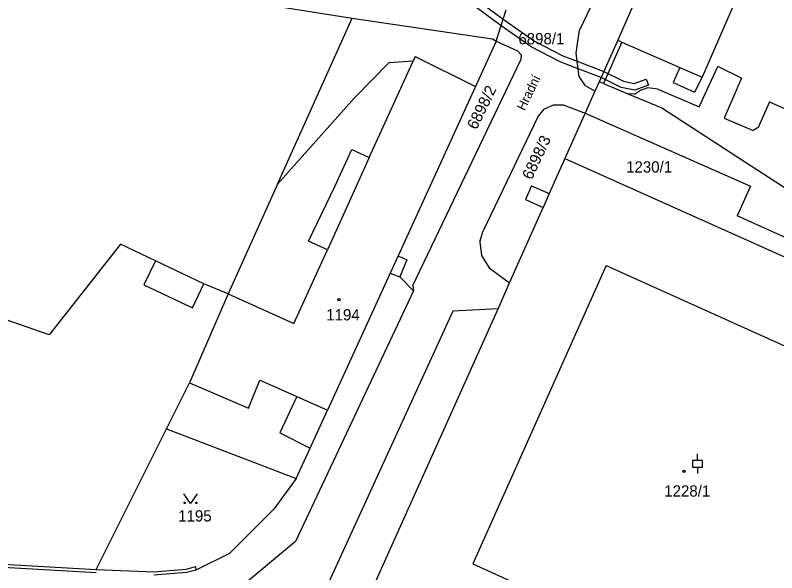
# Model space of a CAD drawing. Extents: x -593183 to -588034, y -1130415 to -1124994.
# Drawn here: x -590909.7 to -590794.7, y -1129085.7 to -1129001.6 of the extents above; entities that cross this region are included whole.
import ezdxf

# ---------------------------------------------------------------- set-up
doc = ezdxf.new("R2010")
doc.units = 0
for name, color, linetype in [('Vrstva 1', 7, 'Continuous'), ('Vrstva 15', 7, 'Continuous'), ('Vrstva 18', 7, 'Continuous'), ('Vrstva 19', 7, 'Continuous'), ('Vrstva 25', 7, 'Continuous'), ('Vrstva 27', 7, 'Continuous'), ('Vrstva 4', 7, 'Continuous')]:
    doc.layers.add(name, color=color, linetype=linetype)

msp = doc.modelspace()

# ---------------------------------------------------------------- linework, layer by layer
at = {"layer": 'Vrstva 1'}
for p, q in [((-590794.6, -1128950.4), (-590818.7, -1129005.38)), ((-590799.57, -1128951.88), (-590824.5, -1129003.84)), ((-590905.87, -1128994.54), (-590858.8, -1129002.06)), ((-590837.04, -1129005.53), (-590835.56, -1129000.8)), ((-590870.07, -1129027.1), (-590858.8, -1129002.06)), ((-590858.8, -1129002.06), (-590837.64, -1129005.16)), ((-590824.98, -1129007.35), (-590824.5, -1129003.84)), ((-590837.04, -1129005.53), (-590840.17, -1129012.37)), ((-590837.64, -1129005.16), (-590837.04, -1129005.53)), ((-590837.04, -1129005.53), (-590833.84, -1129006.96)), ((-590818.7, -1129005.38), (-590821.51, -1129011.66)), ((-590833.84, -1129006.96), (-590833.31, -1129007.56)), ((-590824.51, -1129010.86), (-590824.98, -1129007.35)), ((-590849.64, -1129042.41), (-590833.34, -1129008.35)), ((-590833.31, -1129007.56), (-590833.34, -1129008.35)), ((-590806.41, -1129015.41), (-590803.6, -1129009.34)), ((-590800, -1129011.09), (-590803.6, -1129009.34)), ((-590823.56, -1129012.26), (-590824.51, -1129010.86)), ((-590821.51, -1129011.66), (-590822.14, -1129013.08)), ((-590820.87, -1129011.93), (-590821.51, -1129011.66)), ((-590820.87, -1129011.93), (-590817.17, -1129013.47)), ((-590800, -1129011.09), (-590802.65, -1129017.15)), ((-590840.17, -1129012.37), (-590851.87, -1129037.93)), ((-590822.14, -1129013.08), (-590823.62, -1129016.37)), ((-590822.14, -1129013.08), (-590823.56, -1129012.26)), ((-590816.16, -1129013.5), (-590815.43, -1129012.99)), ((-590814.16, -1129012.57), (-590815.43, -1129012.99)), ((-590812.62, -1129012.75), (-590814.16, -1129012.57)), ((-590812.62, -1129012.75), (-590806.41, -1129015.41)), ((-590816.16, -1129013.5), (-590817.17, -1129013.47)), ((-590817.17, -1129013.47), (-590812.05, -1129015.6)), ((-590829.75, -1129015.71), (-590828.42, -1129015.11)), ((-590828.42, -1129015.11), (-590826.94, -1129015.13)), ((-590826.94, -1129015.13), (-590823.62, -1129016.37)), ((-590795.79, -1129014.65), (-590797.51, -1129018.56)), ((-590795.79, -1129014.65), (-590764.3, -1129028.78)), ((-590830.78, -1129016.94), (-590829.75, -1129015.71)), ((-590823.62, -1129016.37), (-590823.77, -1129016.71)), ((-590823.62, -1129016.37), (-590798.64, -1129027.39)), ((-590812.05, -1129015.6), (-590770.33, -1129042.68)), ((-590830.78, -1129016.94), (-590839.02, -1129034.14)), ((-590823.77, -1129016.71), (-590826.68, -1129023.22)), ((-590802.65, -1129017.15), (-590798.22, -1129019.01)), ((-590797.51, -1129018.56), (-590798.22, -1129019.01)), ((-590826.68, -1129023.22), (-590829.04, -1129028.52)), ((-590826.68, -1129023.22), (-590760.68, -1129052.84)), ((-590904.57, -1129049.84), (-590970.73, -1129026.91)), ((-590870.07, -1129027.1), (-590877.54, -1129043.64)), ((-590798.64, -1129027.39), (-590800.66, -1129031.89)), ((-590829.04, -1129028.52), (-590829.97, -1129030.61)), ((-590835.03, -1129041.99), (-590829.97, -1129030.61)), ((-590768.75, -1129046.27), (-590800.66, -1129031.89)), ((-590839.51, -1129035.82), (-590839.02, -1129034.14)), ((-590893.79, -1129036.15), (-590904.57, -1129049.84)), ((-590888.52, -1129038.67), (-590893.79, -1129036.15)), ((-590839.51, -1129035.82), (-590839.27, -1129037.84)), ((-590851.87, -1129037.93), (-590853.07, -1129040.55)), ((-590839.27, -1129037.84), (-590838.13, -1129039.72)), ((-590881.23, -1129042.15), (-590888.52, -1129038.67)), ((-590853.07, -1129040.55), (-590862.53, -1129061.21)), ((-590853.07, -1129040.55), (-590851.59, -1129041.1)), ((-590838.13, -1129039.72), (-590835.03, -1129041.99)), ((-590851.59, -1129041.1), (-590849.54, -1129043.19)), ((-590877.54, -1129043.64), (-590881.23, -1129042.15)), ((-590849.64, -1129042.41), (-590849.54, -1129043.19)), ((-590836.78, -1129045.92), (-590835.03, -1129041.99)), ((-590877.54, -1129043.64), (-590883.4, -1129057.07)), ((-590849.54, -1129043.19), (-590867.38, -1129081.05)), ((-590843.6, -1129046.27), (-590866.67, -1129096.56)), ((-590857.65, -1129092.4), (-590836.78, -1129045.92)), ((-590836.78, -1129045.92), (-590843.6, -1129046.27)), ((-590886.86, -1129064), (-590883.4, -1129057.07)), ((-590865.18, -1129066.96), (-590862.53, -1129061.21)), ((-590897.47, -1129085.25), (-590886.86, -1129064)), ((-590886.86, -1129064), (-590867.29, -1129071.53)), ((-590867.29, -1129071.53), (-590865.18, -1129066.96)), ((-590867.29, -1129071.53), (-590870.66, -1129076.16)), ((-590870.66, -1129076.16), (-590877.35, -1129082.85)), ((-590867.38, -1129081.05), (-590876.2, -1129088.39)), ((-590877.35, -1129082.85), (-590882.4, -1129085.37)), ((-590916.31, -1129084.19), (-590897.47, -1129085.25)), ((-590897.47, -1129085.25), (-590888.79, -1129085.63)), ((-590888.79, -1129085.63), (-590883.86, -1129085.19)), ((-590883.86, -1129085.19), (-590882.49, -1129084.78)), ((-590882.49, -1129084.78), (-590882.4, -1129085.37))]:
    msp.add_line(p, q, dxfattribs=at)
at = {"layer": 'Vrstva 25'}
for p, q in [((-590806.64, -1129068.79), (-590806.64, -1129067.79)), ((-590806.64, -1129069.79), (-590806.64, -1129070.79))]:
    msp.add_line(p, q, dxfattribs=at)
msp.add_lwpolyline([(-590807.39, -1129069.79), (-590805.89, -1129069.79), (-590805.89, -1129068.79), (-590807.39, -1129068.79)], close=True, dxfattribs=at)
msp.add_lwpolyline([(-590882.23, -1129073.81), (-590883.23, -1129075.31), (-590884.23, -1129073.81)], dxfattribs=at)
for centre, radius in [((-590860.79, -1129044.55), 0.175), ((-590860.79, -1129044.55), 0.15), ((-590808.68, -1129070.44), 0.175), ((-590808.68, -1129070.44), 0.15), ((-590884.13, -1129075.21), 0.1), ((-590882.33, -1129075.21), 0.1)]:
    msp.add_circle(centre, radius, dxfattribs=at)
at = {"layer": 'Vrstva 27'}
for p, q in [((-590840.72, -1128998.7), (-590835.99, -1129002.18)), ((-590836.31, -1129003.19), (-590841.12, -1128999.64)), ((-590835.99, -1129002.18), (-590831.28, -1129005.5)), ((-590831.8, -1129006.36), (-590836.31, -1129003.19)), ((-590831.28, -1129005.5), (-590827, -1129007.72)), ((-590827.42, -1129008.62), (-590831.8, -1129006.36)), ((-590827, -1129007.72), (-590824.82, -1129008.56)), ((-590824.82, -1129008.56), (-590820.81, -1129010.1)), ((-590824.67, -1129009.69), (-590827.42, -1129008.62)), ((-590821.22, -1129011.02), (-590824.67, -1129009.69)), ((-590820.81, -1129010.1), (-590817.83, -1129011.56)), ((-590818.19, -1129012.5), (-590821.22, -1129011.02)), ((-590817.83, -1129011.56), (-590816.21, -1129011.9)), ((-590816.21, -1129011.9), (-590814.43, -1129011.24)), ((-590814.43, -1129011.24), (-590814.05, -1129012.16)), ((-590816.13, -1129012.92), (-590818.19, -1129012.5)), ((-590814.05, -1129012.16), (-590816.13, -1129012.92))]:
    msp.add_line(p, q, dxfattribs=at)
at = {"layer": 'Vrstva 4'}
for p, q in [((-590789.91, -1128974.2), (-590805.97, -1129010.93)), ((-590818.09, -1129005.65), (-590820.87, -1129011.93)), ((-590818.7, -1129005.38), (-590818.09, -1129005.65)), ((-590818.09, -1129005.65), (-590809.33, -1129009.47)), ((-590856.22, -1129023.06), (-590849.62, -1129008.53)), ((-590849.62, -1129008.53), (-590853.25, -1129008.81)), ((-590849.29, -1129007.81), (-590849.62, -1129008.53)), ((-590849.29, -1129007.81), (-590840.17, -1129012.37)), ((-590853.25, -1129008.81), (-590858.45, -1129014.07)), ((-590809.33, -1129009.47), (-590810.34, -1129011.75)), ((-590809.33, -1129009.47), (-590805.97, -1129010.93)), ((-590810.34, -1129011.75), (-590807.13, -1129013.19)), ((-590805.97, -1129010.93), (-590807.13, -1129013.19)), ((-590858.45, -1129014.07), (-590870.07, -1129027.1)), ((-590861.41, -1129027.46), (-590858.86, -1129021.86)), ((-590858.86, -1129021.86), (-590856.22, -1129023.06)), ((-590856.22, -1129023.06), (-590858.77, -1129028.66)), ((-590865.42, -1129035.68), (-590861.41, -1129027.46)), ((-590831.71, -1129027.33), (-590832.64, -1129029.42)), ((-590831.71, -1129027.33), (-590829.04, -1129028.52)), ((-590858.77, -1129028.66), (-590862.56, -1129036.99)), ((-590832.64, -1129029.42), (-590829.97, -1129030.61)), ((-590862.56, -1129036.99), (-590865.42, -1129035.68)), ((-590867.62, -1129048.12), (-590862.56, -1129036.99)), ((-590851.87, -1129037.93), (-590850.55, -1129038.54)), ((-590888.52, -1129038.67), (-590890.27, -1129042.31)), ((-590850.55, -1129038.54), (-590851.59, -1129041.1)), ((-590820.47, -1129039.38), (-590840.61, -1129084.42)), ((-590820.47, -1129039.38), (-590775.49, -1129059.59)), ((-590890.27, -1129042.31), (-590882.95, -1129045.75)), ((-590882.95, -1129045.75), (-590881.23, -1129042.15)), ((-590877.54, -1129043.64), (-590867.62, -1129048.12)), ((-590874.49, -1129060.88), (-590872.76, -1129056.68)), ((-590872.76, -1129056.68), (-590871.59, -1129057.2)), ((-590883.4, -1129057.07), (-590874.49, -1129060.88)), ((-590871.59, -1129057.2), (-590867.19, -1129059.15)), ((-590867.19, -1129059.15), (-590869.74, -1129064.64)), ((-590867.19, -1129059.15), (-590862.53, -1129061.21)), ((-590869.74, -1129064.64), (-590865.18, -1129066.96)), ((-590840.61, -1129084.42), (-590795.3, -1129104.76)), ((-590897.49, -1129085.75), (-590916.33, -1129084.69)), ((-590882.4, -1129085.37), (-590883.82, -1129085.69)), ((-590883.82, -1129085.69), (-590888.78, -1129086.13))]:
    msp.add_line(p, q, dxfattribs=at)

# ---------------------------------------------------------------- texts
at = {"layer": 'Vrstva 15'}
msp.add_text('Hradní', height=1.4, rotation=64.1207, dxfattribs=at).set_placement((-590832.76, -1129016.11))
at = {"layer": 'Vrstva 18'}
for s, p in [('6898/1', (-590833.71, -1129005.99)), ('1230/1', (-590817.44, -1129025.35)), ('1195', (-590885.09, -1129078.01))]:
    msp.add_text(s, height=1.7, dxfattribs=at).set_placement(p)
for s, rotation, p in [('6898/2', 63.9, (-590840.03, -1129018.99)), ('6898/3', 64.8, (-590831.7, -1129026.55))]:
    msp.add_text(s, height=1.7, rotation=rotation, dxfattribs=at).set_placement(p)
at = {"layer": 'Vrstva 19'}
for s, p in [('1194', (-590862.73, -1129047.66)), ('1228/1', (-590811.68, -1129074.25))]:
    msp.add_text(s, height=1.7, dxfattribs=at).set_placement(p)

doc.saveas('drawing.dxf')
